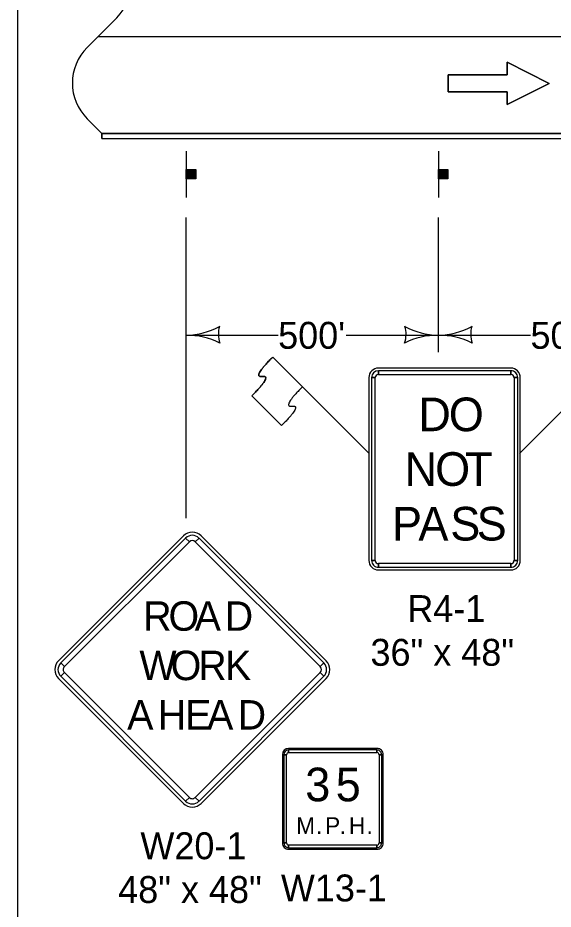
# Model space of a CAD drawing. Extents: x -2134934 to -2122394, y -2140205 to -2137036.
# Drawn here: x -2134934 to -2134616, y -2138126 to -2137596 of the extents above; entities that cross this region are included whole.
import ezdxf

# ---------------------------------------------------------------- set-up
doc = ezdxf.new("R2010")
doc.units = 0
for name, color, linetype in [('Barrier', 7, 'Continuous'), ('BridgeSuperStructureExisting', 7, 'Continuous'), ('Default', 7, 'Continuous'), ('DsnShtPlotIdentification', 7, 'Continuous'), ('TC_Barrier', 7, 'Continuous')]:
    doc.layers.add(name, color=color, linetype=linetype)

msp = doc.modelspace()

# ---------------------------------------------------------------- linework, layer by layer
at = {"layer": 'Barrier'}
for p, q in [((-2134725.6, -2137855.42), (-2134782.94, -2137798.12)), ((-2134782.94, -2137798.12), (-2134765.25, -2137815.8)), ((-2134636.31, -2137855.42), (-2134578.99, -2137798.11)), ((-2134641.36, -2137804.67), (-2134720.11, -2137804.67)), ((-2134720.11, -2137808.42), (-2134720.11, -2137806.23)), ((-2134641.36, -2137806.23), (-2134641.36, -2137808.42)), ((-2134725.73, -2137810.29), (-2134725.73, -2137919.04)), ((-2134724.17, -2137810.29), (-2134721.98, -2137810.29)), ((-2134639.48, -2137810.29), (-2134637.3, -2137810.29)), ((-2134635.73, -2137919.04), (-2134635.73, -2137810.29)), ((-2134777.63, -2137838.79), (-2134795.31, -2137821.12)), ((-2134836.02, -2137904.4), (-2134910.27, -2137978.64)), ((-2134834.69, -2137905.72), (-2134832.48, -2137907.93)), ((-2134828.95, -2137907.93), (-2134826.74, -2137905.72)), ((-2134751.17, -2137978.64), (-2134825.41, -2137904.4)), ((-2134721.98, -2137919.04), (-2134724.17, -2137919.04)), ((-2134720.11, -2137923.1), (-2134720.11, -2137920.91)), ((-2134641.36, -2137920.91), (-2134641.36, -2137923.1)), ((-2134637.3, -2137919.04), (-2134639.48, -2137919.04)), ((-2134720.11, -2137924.66), (-2134641.36, -2137924.66)), ((-2134906.73, -2137982.18), (-2134908.94, -2137979.97)), ((-2134752.49, -2137979.97), (-2134754.7, -2137982.18)), ((-2134908.94, -2137987.92), (-2134906.73, -2137985.71)), ((-2134754.7, -2137985.71), (-2134752.49, -2137987.92)), ((-2134910.27, -2137989.25), (-2134836.02, -2138063.5)), ((-2134825.41, -2138063.5), (-2134751.17, -2137989.25)), ((-2134777.2, -2138034.52), (-2134777.2, -2138087.02)), ((-2134776.26, -2138034.52), (-2134774.7, -2138034.52)), ((-2134720.95, -2138030.77), (-2134773.45, -2138030.77)), ((-2134773.45, -2138033.27), (-2134773.45, -2138031.71)), ((-2134720.95, -2138031.71), (-2134720.95, -2138033.27)), ((-2134719.7, -2138034.52), (-2134718.13, -2138034.52)), ((-2134717.2, -2138087.02), (-2134717.2, -2138034.52)), ((-2134832.48, -2138059.96), (-2134834.69, -2138062.17)), ((-2134826.74, -2138062.17), (-2134828.95, -2138059.96)), ((-2134774.7, -2138087.02), (-2134776.26, -2138087.02)), ((-2134773.45, -2138089.83), (-2134773.45, -2138088.27)), ((-2134720.95, -2138088.27), (-2134720.95, -2138089.83)), ((-2134718.13, -2138087.02), (-2134719.7, -2138087.02)), ((-2134773.45, -2138090.77), (-2134720.95, -2138090.77))]:
    msp.add_line(p, q, dxfattribs=at)
for points in [[(-2134641.36, -2137806.23), (-2134720.11, -2137806.23), (-2134720.11, -2137808.42), (-2134641.36, -2137808.42), (-2134641.36, -2137806.23)], [(-2134724.17, -2137810.29), (-2134724.17, -2137919.04), (-2134721.98, -2137919.04), (-2134721.98, -2137810.29), (-2134724.17, -2137810.29)], [(-2134637.3, -2137919.04), (-2134637.3, -2137810.29), (-2134639.48, -2137810.29), (-2134639.48, -2137919.04), (-2134637.3, -2137919.04)], [(-2134834.69, -2137905.72), (-2134908.94, -2137979.97), (-2134906.73, -2137982.18), (-2134832.48, -2137907.93), (-2134834.69, -2137905.72)], [(-2134752.49, -2137979.97), (-2134826.74, -2137905.72), (-2134828.95, -2137907.93), (-2134754.7, -2137982.18), (-2134752.49, -2137979.97)], [(-2134720.11, -2137923.1), (-2134641.36, -2137923.1), (-2134641.36, -2137920.91), (-2134720.11, -2137920.91), (-2134720.11, -2137923.1)], [(-2134908.94, -2137987.92), (-2134834.69, -2138062.17), (-2134832.48, -2138059.96), (-2134906.73, -2137985.71), (-2134908.94, -2137987.92)], [(-2134826.74, -2138062.17), (-2134752.49, -2137987.92), (-2134754.7, -2137985.71), (-2134828.95, -2138059.96), (-2134826.74, -2138062.17)], [(-2134776.26, -2138034.52), (-2134776.26, -2138087.02), (-2134774.7, -2138087.02), (-2134774.7, -2138034.52), (-2134776.26, -2138034.52)], [(-2134720.95, -2138031.71), (-2134773.45, -2138031.71), (-2134773.45, -2138033.27), (-2134720.95, -2138033.27), (-2134720.95, -2138031.71)], [(-2134718.13, -2138087.02), (-2134718.13, -2138034.52), (-2134719.7, -2138034.52), (-2134719.7, -2138087.02), (-2134718.13, -2138087.02)], [(-2134773.45, -2138089.83), (-2134720.95, -2138089.83), (-2134720.95, -2138088.27), (-2134773.45, -2138088.27), (-2134773.45, -2138089.83)]]:
    msp.add_lwpolyline(points, close=True, dxfattribs=at)
for centre, radius, start, end in [((-2134720.11, -2137810.29), 5.62, 90.0002, 179.9998), ((-2134720.11, -2137810.29), 4.06, 90.0002, 179.9998), ((-2134641.36, -2137810.29), 5.62, 0, 90.0002), ((-2134641.36, -2137810.29), 4.06, 0, 90.0002), ((-2134720.11, -2137810.29), 1.87, 90.0002, 179.9998), ((-2134641.36, -2137810.29), 1.87, 0, 90.0002), ((-2134830.72, -2137909.7), 7.5, 45, 134.9997), ((-2134830.72, -2137909.7), 5.62, 45, 134.9997), ((-2134830.72, -2137909.7), 2.5, 45, 134.9997), ((-2134720.11, -2137919.04), 5.62, 179.9998, 270.0001), ((-2134720.11, -2137919.04), 4.06, 179.9998, 270.0001), ((-2134720.11, -2137919.04), 1.87, 179.9998, 270.0001), ((-2134641.36, -2137919.04), 5.62, 270.0001, 0.0003), ((-2134641.36, -2137919.04), 4.06, 270.0001, 0.0003), ((-2134641.36, -2137919.04), 1.87, 270.0001, 0.0003), ((-2134904.96, -2137983.95), 7.5, 134.9997, 225), ((-2134904.96, -2137983.95), 5.62, 134.9997, 225), ((-2134904.96, -2137983.95), 2.5, 134.9997, 225), ((-2134756.47, -2137983.95), 2.5, 315.0002, 44.9998), ((-2134756.47, -2137983.95), 5.62, 315.0002, 44.9998), ((-2134756.47, -2137983.95), 7.5, 315.0002, 44.9998), ((-2134773.45, -2138034.52), 3.75, 90.0002, 179.9998), ((-2134773.45, -2138034.52), 2.81, 90.0002, 179.9998), ((-2134773.45, -2138034.52), 1.25, 90.0002, 179.9998), ((-2134720.95, -2138034.52), 3.75, 0, 90.0002), ((-2134720.95, -2138034.52), 2.81, 0, 90.0002), ((-2134720.95, -2138034.52), 1.25, 0, 90.0002), ((-2134830.72, -2138058.19), 2.5, 225, 315.0002), ((-2134830.72, -2138058.19), 7.5, 225, 315.0002), ((-2134830.72, -2138058.19), 5.62, 225, 315.0002), ((-2134773.45, -2138087.02), 3.75, 179.9998, 270.0001), ((-2134773.45, -2138087.02), 2.81, 179.9998, 270.0001), ((-2134773.45, -2138087.02), 1.25, 179.9998, 270.0001), ((-2134720.95, -2138087.02), 3.75, 270.0001, 0.0003), ((-2134720.95, -2138087.02), 2.81, 270.0001, 0.0003), ((-2134720.95, -2138087.02), 1.25, 270.0001, 0.0003)]:
    msp.add_arc(centre, radius, start, end, dxfattribs=at)
for points in [[(-2134795.31, -2137821.12), (-2134782.93, -2137808.74), (-2134795.31, -2137810.51), (-2134782.94, -2137798.12)], [(-2134765.25, -2137815.8), (-2134777.62, -2137828.19), (-2134765.25, -2137826.41), (-2134777.63, -2137838.79)]]:
    msp.add_open_spline(points, degree=2, dxfattribs=at)
at = {"layer": 'BridgeSuperStructureExisting'}
for p, q in [((-2134893.23, -2137613.94), (-2134875.66, -2137596.37)), ((-2134875.65, -2137596.37), (-2134893.23, -2137613.95)), ((-2134884.44, -2137665.16), (-2134893.23, -2137656.37)), ((-2134893.23, -2137656.37), (-2134884.44, -2137665.16)), ((-2134884.44, -2137665.16), (-2133384.44, -2137665.16)), ((-2134834.44, -2137675.66), (-2134834.44, -2137703.16)), ((-2134684.44, -2137675.66), (-2134684.44, -2137703.16)), ((-2134834.03, -2137692.11), (-2134834.03, -2137686.52)), ((-2134833.75, -2137686.52), (-2134833.75, -2137692.11)), ((-2134833.48, -2137692.11), (-2134833.48, -2137686.52)), ((-2134833.22, -2137686.52), (-2134833.22, -2137692.11)), ((-2134833, -2137692.11), (-2134833, -2137686.52)), ((-2134832.79, -2137686.52), (-2134832.79, -2137692.11)), ((-2134832.45, -2137692.11), (-2134832.45, -2137686.52)), ((-2134832.19, -2137686.52), (-2134832.19, -2137692.11)), ((-2134831.96, -2137692.11), (-2134831.98, -2137686.52)), ((-2134831.65, -2137686.52), (-2134831.65, -2137692.11)), ((-2134831.27, -2137692.11), (-2134831.27, -2137686.52)), ((-2134830.84, -2137686.52), (-2134830.84, -2137692.11)), ((-2134830.61, -2137692.11), (-2134830.63, -2137686.52)), ((-2134830.2, -2137686.52), (-2134830.18, -2137692.11)), ((-2134829.98, -2137692.11), (-2134829.98, -2137686.52)), ((-2134829.66, -2137686.52), (-2134829.66, -2137692.11)), ((-2134829.43, -2137692.11), (-2134829.43, -2137686.52)), ((-2134829.11, -2137686.52), (-2134829.11, -2137692.11)), ((-2134684.03, -2137692.11), (-2134684.03, -2137686.52)), ((-2134683.75, -2137686.52), (-2134683.75, -2137692.11)), ((-2134683.48, -2137692.11), (-2134683.48, -2137686.52)), ((-2134683.22, -2137686.52), (-2134683.22, -2137692.11)), ((-2134683, -2137692.11), (-2134683, -2137686.52)), ((-2134682.79, -2137686.52), (-2134682.79, -2137692.11)), ((-2134682.45, -2137692.11), (-2134682.45, -2137686.52)), ((-2134682.19, -2137686.52), (-2134682.19, -2137692.11)), ((-2134681.97, -2137692.11), (-2134681.98, -2137686.52)), ((-2134681.65, -2137686.52), (-2134681.65, -2137692.11)), ((-2134681.27, -2137692.11), (-2134681.27, -2137686.52)), ((-2134680.84, -2137686.52), (-2134680.84, -2137692.11)), ((-2134680.62, -2137692.11), (-2134680.63, -2137686.52)), ((-2134680.2, -2137686.52), (-2134680.18, -2137692.11)), ((-2134679.98, -2137692.11), (-2134679.98, -2137686.52)), ((-2134679.66, -2137686.52), (-2134679.66, -2137692.11)), ((-2134679.43, -2137692.11), (-2134679.43, -2137686.52)), ((-2134679.12, -2137686.52), (-2134679.12, -2137692.11)), ((-2134834.44, -2137893.97), (-2134834.44, -2137715.16)), ((-2134684.44, -2137795.16), (-2134684.44, -2137715.16)), ((-2134834.44, -2137785.16), (-2134779.69, -2137785.16)), ((-2134739.19, -2137785.16), (-2134684.44, -2137785.16)), ((-2134684.44, -2137785.16), (-2134629.69, -2137785.16))]:
    msp.add_line(p, q, dxfattribs=at)
for points in [[(-2134678.55, -2137630.33), (-2134678.55, -2137640.33), (-2134643.55, -2137640.33), (-2134643.55, -2137647.83), (-2134618.55, -2137635.33), (-2134643.55, -2137622.83), (-2134643.55, -2137630.33)], [(-2134834.35, -2137692.11), (-2134834.35, -2137686.48), (-2134828.72, -2137686.48), (-2134828.72, -2137692.11)], [(-2134684.35, -2137692.11), (-2134684.35, -2137686.48), (-2134678.72, -2137686.48), (-2134678.72, -2137692.11)]]:
    msp.add_lwpolyline(points, close=True, dxfattribs=at)
msp.add_lwpolyline([(-2134643.55, -2137630.33), (-2134643.55, -2137622.83), (-2134618.55, -2137635.33), (-2134643.55, -2137647.83), (-2134643.55, -2137640.33), (-2134678.55, -2137640.33), (-2134678.55, -2137630.33), (-2134643.55, -2137630.33)], dxfattribs=at)
for centre, radius, start, end in [((-2134896.87, -2137575.16), 30, 315, 45), ((-2134896.87, -2137575.16), 30, 315, 45), ((-2134872.02, -2137635.16), 30, 135, 225), ((-2134872.02, -2137635.16), 30, 135, 225), ((-2134835.2, -2137742.67), 42.5, 271.0176, 299.0725), ((-2134798.82, -2137784.54), 16.42, 163.2666, 198.7334), ((-2134720.06, -2137784.54), 16.42, 341.2666, 16.7334), ((-2134683.69, -2137742.67), 42.5, 240.9275, 268.9824), ((-2134685.2, -2137742.67), 42.5, 271.0176, 299.0725), ((-2134648.82, -2137784.54), 16.42, 163.2666, 198.7334), ((-2134833.71, -2137827.65), 42.5, 62.9275, 90.9824), ((-2134685.17, -2137827.65), 42.5, 89.0176, 117.0725), ((-2134683.71, -2137827.65), 42.5, 62.9275, 90.9824)]:
    msp.add_arc(centre, radius, start, end, dxfattribs=at)
at = {"layer": 'Default'}
msp.add_lwpolyline([(-2134934.44, -2137035.95), (-2131799.45, -2137035.95), (-2131799.45, -2139045.94), (-2134934.44, -2139045.94)], close=True, dxfattribs=at)
at = {"layer": 'DsnShtPlotIdentification'}
for p, q in [((-2134234.44, -2137607.66), (-2134886.94, -2137607.66)), ((-2134884.44, -2137665.16), (-2133384.44, -2137665.16)), ((-2134884.44, -2137665.16), (-2133384.44, -2137665.16)), ((-2134884.44, -2137668.16), (-2134884.44, -2137665.16)), ((-2134239.44, -2137665.16), (-2134884.44, -2137665.16)), ((-2134884.44, -2137665.16), (-2134884.44, -2137668.16)), ((-2134884.44, -2137668.16), (-2133384.44, -2137668.16)), ((-2134884.44, -2137668.16), (-2133384.44, -2137668.16))]:
    msp.add_line(p, q, dxfattribs=at)
at = {"layer": 'TC_Barrier'}
msp.add_line((-2134795.31, -2137821.12), (-2134777.63, -2137838.79), dxfattribs=at)
for points in [[(-2134782.94, -2137798.12), (-2134795.31, -2137810.51), (-2134782.93, -2137808.74), (-2134795.31, -2137821.12)], [(-2134765.25, -2137815.8), (-2134777.62, -2137828.19), (-2134765.25, -2137826.41), (-2134777.63, -2137838.79)]]:
    msp.add_open_spline(points, degree=2, dxfattribs=at)

# ---------------------------------------------------------------- texts
at = {"layer": 'Barrier'}
for s, height, p in [('D', 20, (-2134696.36, -2137842.17)), ('O', 20, (-2134678.23, -2137842.17)), ('N', 20, (-2134704.48, -2137874.67)), ('O', 20, (-2134686.36, -2137874.67)), ('T', 20, (-2134668.55, -2137874.67)), ('S', 20, (-2134677.34, -2137907.17)), ('S', 20, (-2134661.66, -2137907.17)), ('P', 20, (-2134712, -2137907.17)), ('A', 20, (-2134696.31, -2137907.17)), ('R4-1', 16, (-2134702.9, -2137955.66)), ('R', 17.5, (-2134859.88, -2137960.82)), ('O', 17.5, (-2134844.87, -2137960.82)), ('A', 17.5, (-2134829.32, -2137960.82)), ('D', 17.5, (-2134811.44, -2137960.82)), ('36" x 48"', 16, (-2134724.8, -2137981.66)), ('W', 17.5, (-2134862.16, -2137990.2)), ('O', 17.5, (-2134843.57, -2137990.2)), ('R', 17.5, (-2134827.16, -2137990.2)), ('K', 17.5, (-2134811.3, -2137990.2)), ('A', 17.5, (-2134869.44, -2138019.57)), ('H', 17.5, (-2134851.23, -2138019.57)), ('E', 17.5, (-2134835, -2138019.57)), ('A', 17.5, (-2134821.96, -2138019.57)), ('D', 17.5, (-2134803.75, -2138019.57)), ('3', 20, (-2134763.58, -2138062.23)), ('5', 20, (-2134745.46, -2138062.23)), ('M', 10, (-2134768.97, -2138081.71)), ('P', 10, (-2134751.72, -2138081.71)), ('H', 10, (-2134737.6, -2138081.71)), ('W20-1', 16, (-2134861.57, -2138096.69)), ('.', 10, (-2134757.18, -2138081.71)), ('.', 10, (-2134743.06, -2138081.71)), ('.', 10, (-2134727.13, -2138081.71)), ('48" x 48"', 16, (-2134874.78, -2138122.69)), ('W13-1', 16, (-2134778.05, -2138121.77))]:
    msp.add_text(s, height=height, dxfattribs=at).set_placement(p)
at = {"layer": 'BridgeSuperStructureExisting'}
for p in [(-2134779.69, -2137793.16), (-2134629.69, -2137793.16)]:
    msp.add_text("500'", height=16, dxfattribs=at).set_placement(p)

doc.saveas('drawing.dxf')
